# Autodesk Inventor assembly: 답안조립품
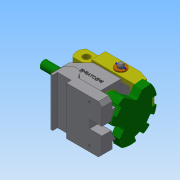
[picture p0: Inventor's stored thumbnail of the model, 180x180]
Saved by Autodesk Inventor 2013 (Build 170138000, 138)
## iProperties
Created: 2016-11
Part Number: 답안조립품
Document SubType Name: Assembly
Designer: user
Author: user
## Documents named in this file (8)
- C:\Users\user\Desktop\461108V1023\답안조립품.iam
- C:\Users\user\Desktop\461108V1023\본체.ipt
- C:\Users\user\Desktop\461108V1023\부시.ipt
- C:\Users\user\Desktop\461108V1023\분할대.ipt
- C:\Users\user\Desktop\461108V1023\분할축.ipt
- C:\Users\user\Desktop\461108V1023\와셔.ipt
- C:\Users\user\Desktop\461108V1023\원통형핀.ipt
- C:\Users\user\Desktop\461108V1023\클레비스핀.ipt
